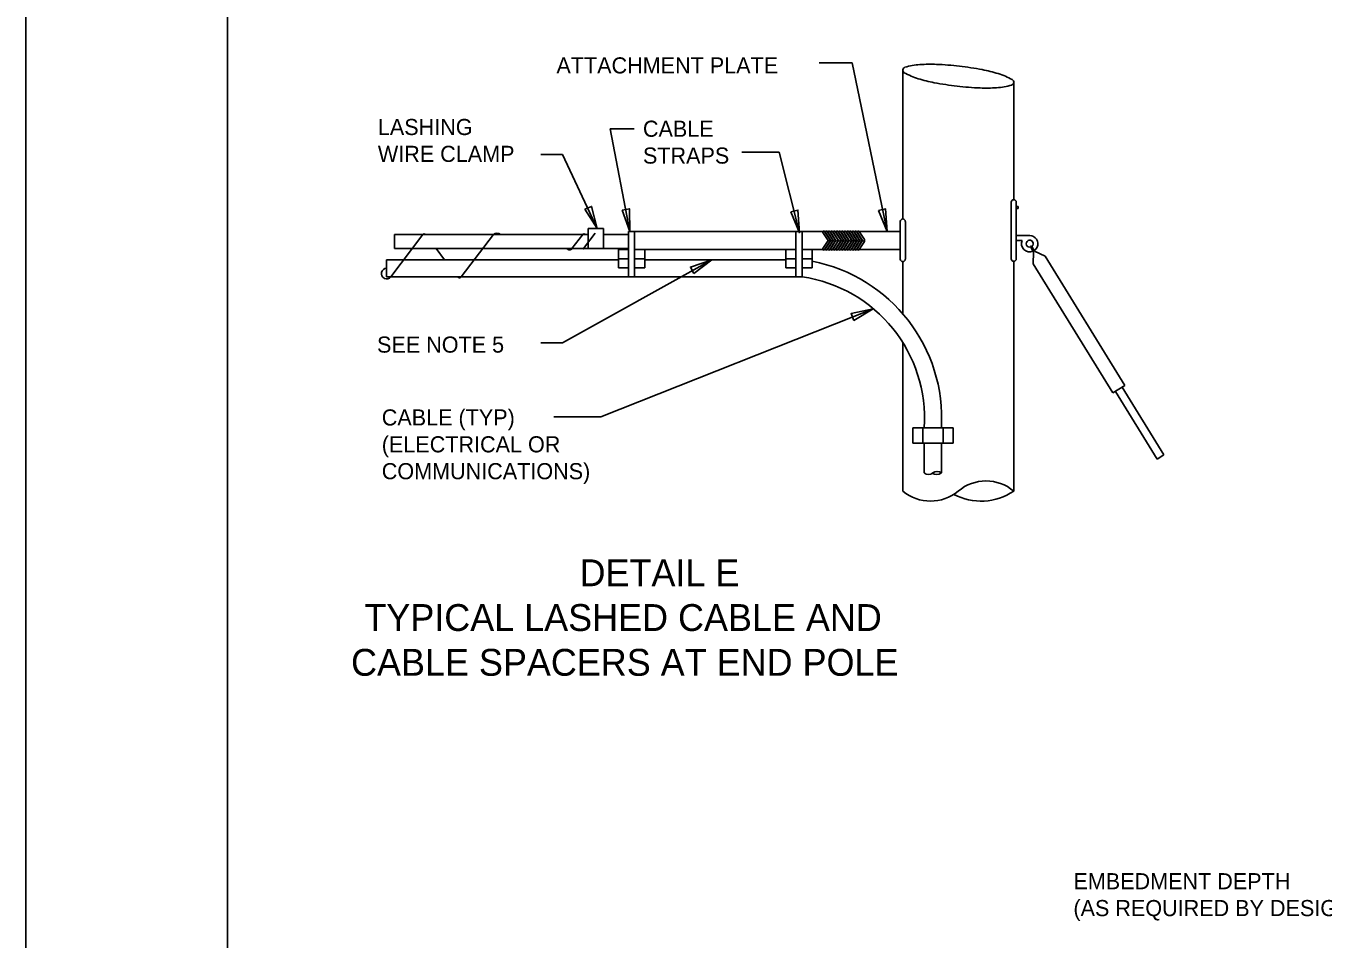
# Model space of a CAD drawing. Extents: x 1299104.8 to 1299141.6, y 239639.8 to 239661.8.
# Drawn here: x 1299104.8 to 1299114.45, y 239646.46 to 239653.26 of the extents above; entities that cross this region are included whole.
import ezdxf

# ---------------------------------------------------------------- set-up
doc = ezdxf.new("R2010")
doc.units = 0
for name, color, linetype in [('DIM TXT', 7, 'Continuous'), ('GS_plotshape_p', 7, 'Continuous'), ('Level 1', 7, 'Continuous')]:
    doc.layers.add(name, color=color, linetype=linetype)

msp = doc.modelspace()

# ---------------------------------------------------------------- linework, layer by layer
at = {"layer": 'DIM TXT'}
for p, q in [((1299110.9475, 239652.984), (1299110.7022, 239652.984)), ((1299111.2088, 239651.7283), (1299110.9475, 239652.984)), ((1299111.3253, 239651.8219), (1299111.3253, 239652.9323)), ((1299112.1503, 239651.9647), (1299112.1503, 239652.8373)), ((1299109.2936, 239651.7283), (1299109.1482, 239652.4937)), ((1299109.1482, 239652.4937), (1299109.3276, 239652.4937)), ((1299108.7937, 239652.3028), (1299108.6324, 239652.3028)), ((1299109.0505, 239651.7508), (1299108.7937, 239652.3028)), ((1299110.1265, 239652.3194), (1299110.4059, 239652.3194)), ((1299110.4059, 239652.3194), (1299110.5566, 239651.7192)), ((1299112.1316, 239651.9459), (1299112.1316, 239651.5259)), ((1299112.1691, 239651.9459), (1299112.1691, 239651.5259)), ((1299112.1691, 239651.9154), (1299112.1841, 239651.9154)), ((1299112.1691, 239651.9004), (1299112.1841, 239651.9004)), ((1299112.1841, 239651.9154), (1299112.1841, 239651.9004)), ((1299109.0978, 239651.7508), (1299108.9853, 239651.7508)), ((1299108.9853, 239651.6008), (1299108.9853, 239651.7508)), ((1299109.0978, 239651.6008), (1299109.0978, 239651.7508)), ((1299111.3066, 239651.8031), (1299111.3066, 239651.5225)), ((1299111.3441, 239651.8031), (1299111.3441, 239651.5225)), ((1299107.7555, 239651.7058), (1299107.5167, 239651.3909)), ((1299108.9853, 239651.7058), (1299107.544, 239651.7058)), ((1299107.544, 239651.6008), (1299107.544, 239651.7058)), ((1299108.2796, 239651.7058), (1299108.0408, 239651.3909)), ((1299108.9438, 239651.7058), (1299108.8642, 239651.6008)), ((1299109.0371, 239651.7164), (1299108.9495, 239651.6008)), ((1299109.2853, 239651.7058), (1299109.0978, 239651.7058)), ((1299109.2853, 239651.3909), (1299109.2853, 239651.7283)), ((1299109.2853, 239651.7283), (1299109.3303, 239651.7283)), ((1299110.7306, 239651.7283), (1299109.3303, 239651.7283)), ((1299109.3303, 239651.3909), (1299109.3303, 239651.7283)), ((1299110.5303, 239651.3909), (1299110.5303, 239651.7283)), ((1299110.5303, 239651.7283), (1299110.5753, 239651.7283)), ((1299110.5753, 239651.3909), (1299110.5753, 239651.7283)), ((1299110.7306, 239651.7202), (1299110.7688, 239651.6608)), ((1299110.7688, 239651.6608), (1299110.7306, 239651.6015)), ((1299110.7506, 239651.7283), (1299110.7432, 239651.7283)), ((1299110.7432, 239651.7283), (1299110.7814, 239651.669)), ((1299110.7814, 239651.6527), (1299110.7432, 239651.5933)), ((1299110.7506, 239651.7202), (1299110.7888, 239651.6608)), ((1299110.7888, 239651.6608), (1299110.7506, 239651.6015)), ((1299110.7698, 239651.7283), (1299110.7632, 239651.7283)), ((1299110.7632, 239651.7283), (1299110.8014, 239651.669)), ((1299110.8014, 239651.6527), (1299110.7632, 239651.5933)), ((1299110.7698, 239651.7202), (1299110.808, 239651.6608)), ((1299110.808, 239651.6608), (1299110.7698, 239651.6015)), ((1299110.7899, 239651.7283), (1299110.7824, 239651.7283)), ((1299110.7824, 239651.7283), (1299110.8206, 239651.669)), ((1299110.8206, 239651.6527), (1299110.7824, 239651.5933)), ((1299110.7899, 239651.7202), (1299110.8281, 239651.6608)), ((1299110.8281, 239651.6608), (1299110.7899, 239651.6015)), ((1299110.8098, 239651.7283), (1299110.8025, 239651.7283)), ((1299110.8025, 239651.7283), (1299110.8407, 239651.669)), ((1299110.8407, 239651.6527), (1299110.8025, 239651.5933)), ((1299110.8098, 239651.7202), (1299110.848, 239651.6608)), ((1299110.848, 239651.6608), (1299110.8098, 239651.6015)), ((1299110.8298, 239651.7283), (1299110.8224, 239651.7283)), ((1299110.8224, 239651.7283), (1299110.8606, 239651.669)), ((1299110.8606, 239651.6527), (1299110.8224, 239651.5933)), ((1299110.8298, 239651.7202), (1299110.868, 239651.6608)), ((1299110.868, 239651.6608), (1299110.8298, 239651.6015)), ((1299110.8491, 239651.7283), (1299110.8425, 239651.7283)), ((1299110.8425, 239651.7283), (1299110.8807, 239651.669)), ((1299110.8807, 239651.6527), (1299110.8425, 239651.5933)), ((1299110.8491, 239651.7202), (1299110.8873, 239651.6608)), ((1299110.8873, 239651.6608), (1299110.8491, 239651.6015)), ((1299110.8691, 239651.7283), (1299110.8617, 239651.7283)), ((1299110.8617, 239651.7283), (1299110.8999, 239651.669)), ((1299110.8999, 239651.6527), (1299110.8617, 239651.5933)), ((1299110.8691, 239651.7202), (1299110.9073, 239651.6608)), ((1299110.9073, 239651.6608), (1299110.8691, 239651.6015)), ((1299110.889, 239651.7283), (1299110.8817, 239651.7283)), ((1299110.8817, 239651.7283), (1299110.9199, 239651.669)), ((1299110.9199, 239651.6527), (1299110.8817, 239651.5933)), ((1299110.889, 239651.7202), (1299110.9272, 239651.6608)), ((1299110.9272, 239651.6608), (1299110.889, 239651.6015)), ((1299110.9091, 239651.7283), (1299110.9017, 239651.7283)), ((1299110.9017, 239651.7283), (1299110.9399, 239651.669)), ((1299110.9399, 239651.6527), (1299110.9017, 239651.5933)), ((1299110.9091, 239651.7202), (1299110.9473, 239651.6608)), ((1299110.9473, 239651.6608), (1299110.9091, 239651.6015)), ((1299110.9283, 239651.7283), (1299110.9217, 239651.7283)), ((1299110.9217, 239651.7283), (1299110.9599, 239651.669)), ((1299110.9599, 239651.6527), (1299110.9217, 239651.5933)), ((1299110.9283, 239651.7202), (1299110.9665, 239651.6608)), ((1299110.9665, 239651.6608), (1299110.9283, 239651.6015)), ((1299110.9483, 239651.7283), (1299110.9409, 239651.7283)), ((1299110.9409, 239651.7283), (1299110.9791, 239651.669)), ((1299110.9791, 239651.6527), (1299110.9409, 239651.5933)), ((1299110.9483, 239651.7202), (1299110.9865, 239651.6608)), ((1299110.9865, 239651.6608), (1299110.9483, 239651.6015)), ((1299110.9683, 239651.7283), (1299110.9609, 239651.7283)), ((1299110.9609, 239651.7283), (1299110.9991, 239651.669)), ((1299110.9991, 239651.6527), (1299110.9609, 239651.5933)), ((1299110.9683, 239651.7202), (1299111.0065, 239651.6608)), ((1299111.0065, 239651.6608), (1299110.9683, 239651.6015)), ((1299110.9809, 239651.7283), (1299111.0191, 239651.669)), ((1299110.9883, 239651.7283), (1299110.9809, 239651.7283)), ((1299111.0191, 239651.6527), (1299110.9809, 239651.5933)), ((1299110.9883, 239651.7202), (1299111.0265, 239651.6608)), ((1299111.0265, 239651.6608), (1299110.9883, 239651.6015)), ((1299111.0009, 239651.7283), (1299111.0391, 239651.669)), ((1299111.3066, 239651.7283), (1299111.0009, 239651.7283)), ((1299111.0391, 239651.6527), (1299111.0009, 239651.5933)), ((1299112.1691, 239651.6989), (1299112.2691, 239651.6989)), ((1299112.1691, 239651.6614), (1299112.2127, 239651.6614)), ((1299108.9853, 239651.6008), (1299107.544, 239651.6008)), ((1299107.9158, 239651.5183), (1299107.8533, 239651.6008)), ((1299108.9853, 239651.6008), (1299109.0978, 239651.6008)), ((1299109.2853, 239651.6008), (1299109.0978, 239651.6008)), ((1299109.2103, 239651.4583), (1299109.2103, 239651.5933)), ((1299109.2103, 239651.5933), (1299109.2853, 239651.5933)), ((1299109.3303, 239651.5933), (1299109.4053, 239651.5933)), ((1299110.4553, 239651.5933), (1299109.4053, 239651.5933)), ((1299109.4053, 239651.4583), (1299109.4053, 239651.5933)), ((1299110.4553, 239651.4583), (1299110.4553, 239651.5933)), ((1299110.4553, 239651.5933), (1299110.5303, 239651.5933)), ((1299110.5753, 239651.5933), (1299110.6503, 239651.5933)), ((1299110.6503, 239651.4583), (1299110.6503, 239651.5933)), ((1299110.7306, 239651.5933), (1299110.6503, 239651.5933)), ((1299110.7506, 239651.5933), (1299110.7432, 239651.5933)), ((1299110.7698, 239651.5933), (1299110.7632, 239651.5933)), ((1299110.7899, 239651.5933), (1299110.7824, 239651.5933)), ((1299110.8098, 239651.5933), (1299110.8025, 239651.5933)), ((1299110.8298, 239651.5933), (1299110.8224, 239651.5933)), ((1299110.8491, 239651.5933), (1299110.8425, 239651.5933)), ((1299110.8691, 239651.5933), (1299110.8617, 239651.5933)), ((1299110.889, 239651.5933), (1299110.8817, 239651.5933)), ((1299110.9091, 239651.5933), (1299110.9017, 239651.5933)), ((1299110.9283, 239651.5933), (1299110.9217, 239651.5933)), ((1299110.9483, 239651.5933), (1299110.9409, 239651.5933)), ((1299110.9683, 239651.5933), (1299110.9609, 239651.5933)), ((1299110.9883, 239651.5933), (1299110.9809, 239651.5933)), ((1299111.3066, 239651.5933), (1299111.0009, 239651.5933)), ((1299112.2832, 239651.6212), (1299112.2748, 239651.6167)), ((1299112.2973, 239651.575), (1299112.2748, 239651.6167)), ((1299112.3045, 239651.5815), (1299112.2832, 239651.6212)), ((1299112.2951, 239651.4886), (1299112.2973, 239651.575)), ((1299112.3045, 239651.5815), (1299112.3845, 239651.5436)), ((1299109.2103, 239651.5183), (1299107.4853, 239651.5183)), ((1299107.4853, 239651.3909), (1299107.4853, 239651.5183)), ((1299109.9046, 239651.5183), (1299108.7937, 239650.8992)), ((1299109.2853, 239651.5258), (1299109.2103, 239651.5258)), ((1299109.2853, 239651.4583), (1299109.2103, 239651.4583)), ((1299109.4053, 239651.5258), (1299109.3303, 239651.5258)), ((1299109.4053, 239651.4583), (1299109.3303, 239651.4583)), ((1299110.4553, 239651.5183), (1299109.4053, 239651.5183)), ((1299110.5303, 239651.5258), (1299110.4553, 239651.5258)), ((1299110.5303, 239651.4583), (1299110.4553, 239651.4583)), ((1299110.6503, 239651.5258), (1299110.5753, 239651.5258)), ((1299110.6503, 239651.4583), (1299110.5753, 239651.4583)), ((1299111.3253, 239651.1156), (1299111.3253, 239651.5038)), ((1299112.1503, 239649.7961), (1299112.1503, 239651.5072)), ((1299112.2951, 239651.4886), (1299112.8871, 239650.5264)), ((1299112.3845, 239651.5436), (1299112.9766, 239650.5814)), ((1299109.2853, 239651.3909), (1299107.4853, 239651.3909)), ((1299109.2853, 239651.3909), (1299109.3303, 239651.3909)), ((1299110.5303, 239651.3909), (1299109.3303, 239651.3909)), ((1299110.5303, 239651.3909), (1299110.5753, 239651.3909)), ((1299111.1058, 239651.1536), (1299109.0794, 239650.3485)), ((1299108.7937, 239650.8992), (1299108.6324, 239650.8992)), ((1299111.3253, 239649.7961), (1299111.3253, 239650.9012)), ((1299112.8871, 239650.5264), (1299112.9766, 239650.5814)), ((1299112.9063, 239650.5382), (1299113.2167, 239650.0337)), ((1299112.9574, 239650.5696), (1299113.2678, 239650.0652)), ((1299109.0794, 239650.3485), (1299108.7295, 239650.3485)), ((1299111.4003, 239650.1534), (1299111.4003, 239650.2659)), ((1299111.7003, 239650.2659), (1299111.4003, 239650.2659)), ((1299111.4753, 239650.1534), (1299111.4753, 239650.2659)), ((1299111.6253, 239650.1534), (1299111.6253, 239650.2659)), ((1299111.7003, 239650.1534), (1299111.7003, 239650.2659)), ((1299111.7003, 239650.1534), (1299111.4003, 239650.1534)), ((1299111.4845, 239650.1534), (1299111.4845, 239649.931)), ((1299111.612, 239650.1534), (1299111.612, 239649.9315)), ((1299113.2167, 239650.0337), (1299113.2678, 239650.0652))]:
    msp.add_line(p, q, dxfattribs=at)
for points in [[(1299108.9604, 239651.8939), (1299109.0105, 239651.9151), (1299109.0505, 239651.7508)], [(1299109.2382, 239651.8881), (1299109.2917, 239651.8974), (1299109.2936, 239651.7283)], [(1299110.4917, 239651.8752), (1299110.5446, 239651.8878), (1299110.5566, 239651.7192)], [(1299111.1439, 239651.8844), (1299111.1968, 239651.897), (1299111.2088, 239651.7283)], [(1299109.7706, 239651.4153), (1299109.7449, 239651.4632), (1299109.9046, 239651.5183)], [(1299110.9611, 239651.0663), (1299110.9408, 239651.1167), (1299111.1058, 239651.1536)]]:
    msp.add_lwpolyline(points, close=True, dxfattribs=at)
for centre, radius, start, end in [((1299111.3471, 239652.9298), 0.0219, 173.42757, 239.86732), ((1299111.3471, 239652.9298), 0.0219, 106.98781, 173.42757), ((1299111.5814, 239653.3335), 0.4887, 239.86732, 253.18901), ((1299111.4835, 239652.4834), 0.4887, 93.66612, 106.98781), ((1299111.528, 239651.7888), 1.1847, 87.70627, 93.66612), ((1299111.4834, 239650.6768), 2.2976, 83.42757, 87.70627), ((1299111.4834, 239650.6768), 2.2976, 79.14886, 83.42757), ((1299111.693, 239651.7698), 1.1847, 73.18901, 79.14886), ((1299111.8943, 239652.4361), 0.4887, 59.86732, 73.18901), ((1299111.7827, 239653.9998), 1.1847, 253.18901, 259.14886), ((1299111.9922, 239655.0928), 2.2976, 259.14886, 263.42757), ((1299111.9922, 239655.0928), 2.2976, 263.42757, 267.70627), ((1299111.9922, 239653.2862), 0.4887, 273.66612, 286.98781), ((1299112.1286, 239652.8398), 0.0219, 286.98781, 353.42757), ((1299112.1286, 239652.8398), 0.0219, 353.42757, 59.86732), ((1299111.9477, 239653.9808), 1.1847, 267.70627, 273.66612), ((1299112.1503, 239651.9459), 0.0187, 0, 180), ((1299111.3253, 239651.8031), 0.0187, 0, 180), ((1299107.7646, 239651.6999), 0.0109, 33.21794, 146.78206), ((1299108.3059, 239651.6728), 0.0423, 51.49023, 128.50977), ((1299108.9535, 239651.6986), 0.0121, 37.01713, 142.98287), ((1299110.7369, 239651.7243), 0.0075, 32.75282, 212.75282), ((1299110.7569, 239651.7243), 0.0075, 32.75282, 212.75282), ((1299110.7761, 239651.7243), 0.0075, 32.75282, 212.75282), ((1299110.7751, 239651.6649), 0.0075, 212.75282, 32.75282), ((1299110.7751, 239651.6568), 0.0075, 327.24718, 32.75282), ((1299110.7962, 239651.7243), 0.0075, 32.75282, 212.75282), ((1299110.7951, 239651.6649), 0.0075, 212.75282, 32.75282), ((1299110.7951, 239651.6568), 0.0075, 327.24718, 32.75282), ((1299110.8143, 239651.6649), 0.0075, 212.75282, 32.75282), ((1299110.8161, 239651.7243), 0.0075, 32.75282, 212.75282), ((1299110.8143, 239651.6568), 0.0075, 327.24718, 32.75282), ((1299110.8344, 239651.6649), 0.0075, 212.75282, 32.75282), ((1299110.8361, 239651.7243), 0.0075, 32.75282, 212.75282), ((1299110.8344, 239651.6568), 0.0075, 327.24718, 32.75282), ((1299110.8554, 239651.7243), 0.0075, 32.75282, 212.75282), ((1299110.8543, 239651.6649), 0.0075, 212.75282, 32.75282), ((1299110.8543, 239651.6568), 0.0075, 327.24718, 32.75282), ((1299110.8754, 239651.7243), 0.0075, 32.75282, 212.75282), ((1299110.8743, 239651.6649), 0.0075, 212.75282, 32.75282), ((1299110.8743, 239651.6568), 0.0075, 327.24718, 32.75282), ((1299110.8936, 239651.6649), 0.0075, 212.75282, 32.75282), ((1299110.8953, 239651.7243), 0.0075, 32.75282, 212.75282), ((1299110.8936, 239651.6568), 0.0075, 327.24718, 32.75282), ((1299110.9136, 239651.6649), 0.0075, 212.75282, 32.75282), ((1299110.9154, 239651.7243), 0.0075, 32.75282, 212.75282), ((1299110.9136, 239651.6568), 0.0075, 327.24718, 32.75282), ((1299110.9346, 239651.7243), 0.0075, 32.75282, 212.75282), ((1299110.9335, 239651.6649), 0.0075, 212.75282, 32.75282), ((1299110.9335, 239651.6568), 0.0075, 327.24718, 32.75282), ((1299110.9546, 239651.7243), 0.0075, 32.75282, 212.75282), ((1299110.9536, 239651.6649), 0.0075, 212.75282, 32.75282), ((1299110.9536, 239651.6568), 0.0075, 327.24718, 32.75282), ((1299110.9728, 239651.6649), 0.0075, 212.75282, 32.75282), ((1299110.9746, 239651.7243), 0.0075, 32.75282, 212.75282), ((1299110.9728, 239651.6568), 0.0075, 327.24718, 32.75282), ((1299110.9928, 239651.6649), 0.0075, 212.75282, 32.75282), ((1299110.9946, 239651.7243), 0.0075, 32.75282, 212.75282), ((1299110.9928, 239651.6568), 0.0075, 327.24718, 32.75282), ((1299111.0128, 239651.6649), 0.0075, 212.75282, 32.75282), ((1299111.0128, 239651.6568), 0.0075, 327.24718, 32.75282), ((1299111.0328, 239651.6649), 0.0075, 212.75282, 32.75282), ((1299111.0328, 239651.6568), 0.0075, 327.24718, 32.75282), ((1299112.2691, 239651.6377), 0.0612, 157.22558, 293.64255), ((1299112.2691, 239651.6377), 0.0259, 308.46642, 287.3643), ((1299112.2691, 239651.6377), 0.0612, 334.64706, 90), ((1299108.8458, 239651.6135), 0.0223, 214.62132, 325.37868), ((1299108.9484, 239651.6012), 0.00109, 198.27859, 341.72141), ((1299110.7369, 239651.5974), 0.0075, 147.24718, 327.24718), ((1299110.7569, 239651.5974), 0.0075, 147.24718, 327.24718), ((1299110.7761, 239651.5974), 0.0075, 147.24718, 327.24718), ((1299110.7962, 239651.5974), 0.0075, 147.24718, 327.24718), ((1299110.8161, 239651.5974), 0.0075, 147.24718, 327.24718), ((1299110.8361, 239651.5974), 0.0075, 147.24718, 327.24718), ((1299110.8554, 239651.5974), 0.0075, 147.24718, 327.24718), ((1299110.8754, 239651.5974), 0.0075, 147.24718, 327.24718), ((1299110.8953, 239651.5974), 0.0075, 147.24718, 327.24718), ((1299110.9154, 239651.5974), 0.0075, 147.24718, 327.24718), ((1299110.9346, 239651.5974), 0.0075, 147.24718, 327.24718), ((1299110.9546, 239651.5974), 0.0075, 147.24718, 327.24718), ((1299110.9746, 239651.5974), 0.0075, 147.24718, 327.24718), ((1299110.9946, 239651.5974), 0.0075, 147.24718, 327.24718), ((1299112.2691, 239651.6377), 0.0612, 302.55083, 334.64706), ((1299107.4857, 239651.4152), 0.0394, 90.50415, 321.92714), ((1299110.4225, 239650.3375), 1.1919, 356.55572, 78.97914), ((1299111.3253, 239651.5225), 0.0187, 180, 0), ((1299112.1503, 239651.5259), 0.0187, 180, 0), ((1299108.0266, 239651.3999), 0.0168, 212.51792, 327.48208), ((1299110.4225, 239650.3375), 1.0644, 356.14257, 81.74353), ((1299111.5165, 239649.9692), 0.0499, 230.03379, 309.96621), ((1299111.5748, 239649.9867), 0.0673, 242.14831, 304.20546), ((1299111.5806, 239649.8928), 0.0499, 50.03379, 129.96621), ((1299111.9441, 239649.55), 0.3211, 50.03379, 129.96621), ((1299111.5316, 239650.0422), 0.3211, 230.03379, 309.96621), ((1299111.9066, 239650.1547), 0.4336, 242.14831, 304.20546)]:
    msp.add_arc(centre, radius, start, end, dxfattribs=at)
at = {"layer": 'GS_plotshape_p'}
msp.add_lwpolyline([(1299104.8019, 239661.7913), (1299138.8019, 239661.7913), (1299138.8019, 239639.7913), (1299104.8019, 239639.7913)], close=True, dxfattribs=at)
at = {"layer": 'Level 1'}
msp.add_lwpolyline([(1299138.3019, 239640.2913), (1299106.3019, 239640.2913), (1299106.3019, 239661.2913), (1299138.3019, 239661.2913)], close=True, dxfattribs=at)

# ---------------------------------------------------------------- texts
at = {"layer": 'DIM TXT'}
for s, height, p in [('ATTACHMENT PLATE', 0.12, (1299108.7484, 239652.905)), ('LASHING ', 0.12, (1299107.42, 239652.4463)), ('CABLE ', 0.12, (1299109.3921, 239652.4336)), ('WIRE CLAMP', 0.12, (1299107.42, 239652.2463)), ('STRAPS', 0.12, (1299109.3921, 239652.2336)), ('SEE NOTE 5', 0.12, (1299107.4138, 239650.8265)), ('CABLE (TYP) ', 0.12, (1299107.449, 239650.2841)), ('(ELECTRICAL OR ', 0.12, (1299107.449, 239650.0841)), ('COMMUNICATIONS)', 0.12, (1299107.449, 239649.8841)), ('DETAIL E', 0.2, (1299108.9204, 239649.0876)), ('TYPICAL LASHED CABLE AND ', 0.2, (1299107.3196, 239648.7543)), ('CABLE SPACERS AT END POLE', 0.2, (1299107.2204, 239648.4209)), ('EMBEDMENT DEPTH', 0.12, (1299112.5944, 239646.8314)), ('(AS REQUIRED BY DESIGN)', 0.12, (1299112.5944, 239646.6314))]:
    msp.add_text(s, height=height, dxfattribs=at).set_placement(p)

doc.saveas('drawing.dxf')
